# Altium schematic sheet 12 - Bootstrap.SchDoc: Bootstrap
size A3; PageSetup: Record=PageOptions¦CenterHorizontal=True¦CenterVertical=True¦PrintScale=1.01¦XCorrection=1.00¦YCorrection=1.00¦PrintKind=0¦BorderSize=5000000¦LeftOffset=0¦BottomOffset=0¦Orientation=2¦PaperLength=4200¦PaperWidth=2970¦Scale=100¦PaperSource=15¦PrintQuality=600¦MediaType=1¦DitherType=10¦PrintScaleMode=1¦PaperKind=A3¦PaperIndex=8; Author: Sébastien MEYER; SheetNumber: 12; SheetTotal: 14
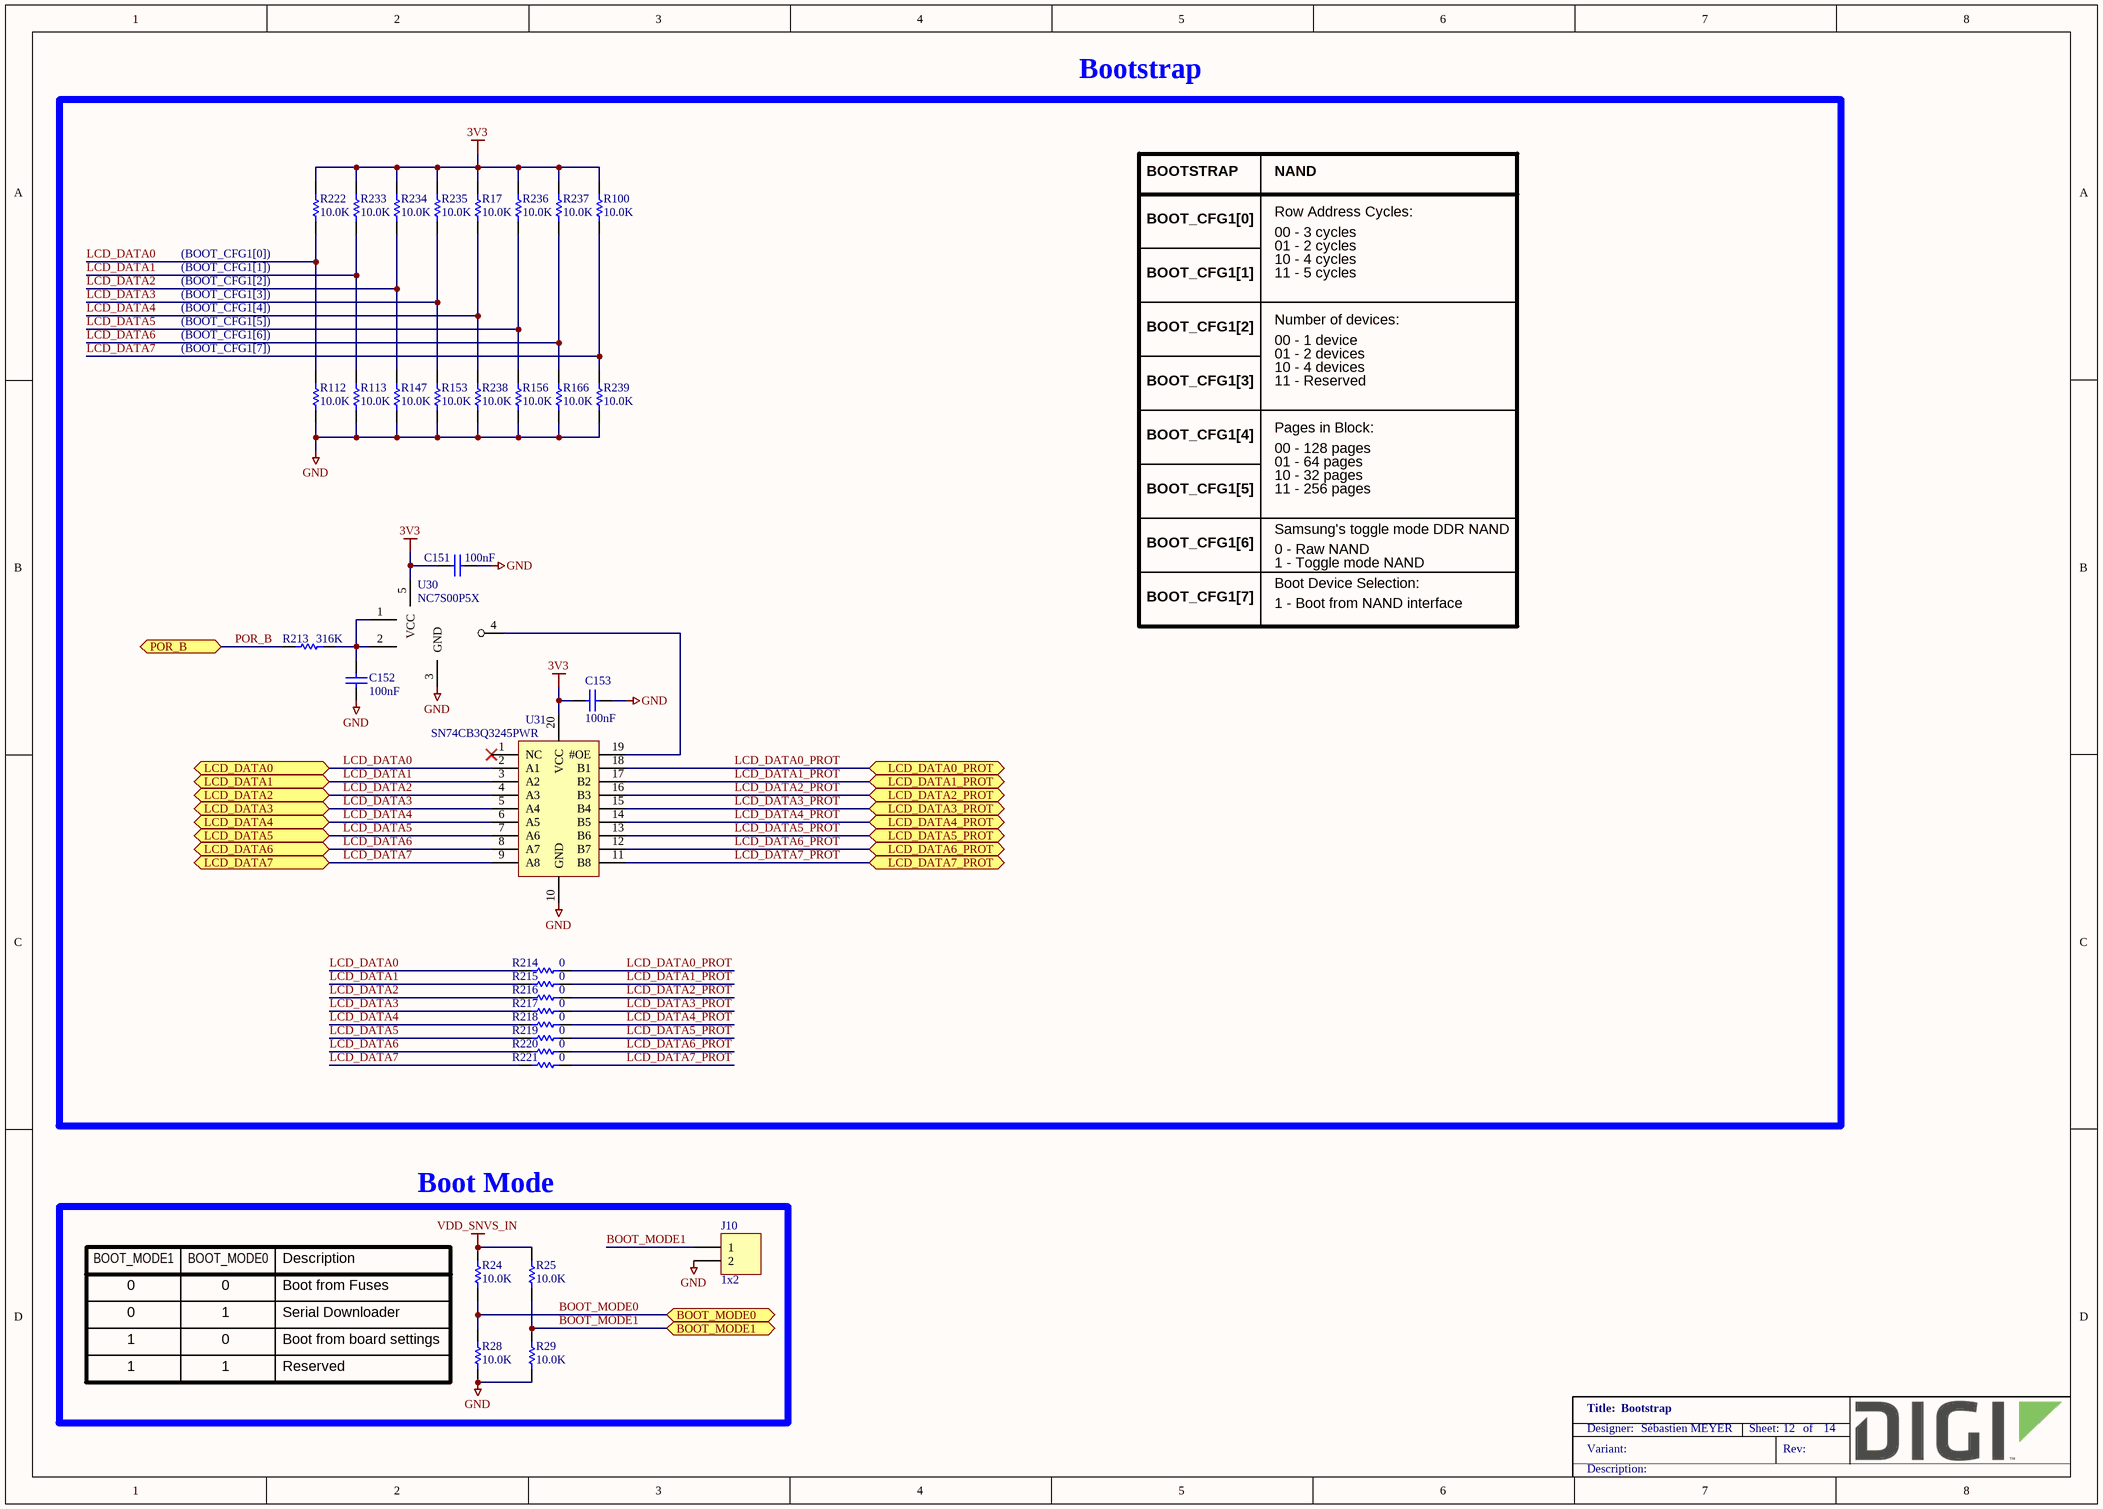
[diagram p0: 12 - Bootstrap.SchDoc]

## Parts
C151  100nF  [CAPC1005X55N]
C152  100nF  [CAPC1005X55N]
C153  100nF  [CAPC1005X55N]
J10  1x2  [FCI_68002-102HLF]
R17  10.0K  [RESC1005X40N]
R24  10.0K  [RESC1005X40N]
R25  10.0K  [RESC1005X40N]
R28  10.0K  [RESC1005X40N]
R29  10.0K  [RESC1005X40N]
R100  10.0K  [RESC1005X40N]
R112  10.0K  [RESC1005X40N]
R113  10.0K  [RESC1005X40N]
R147  10.0K  [RESC1005X40N]
R153  10.0K  [RESC1005X40N]
R156  10.0K  [RESC1005X40N]
R166  10.0K  [RESC1005X40N]
R213  316K  [RESC1609X55N]
R214  0  [RESC1005X40N]
R215  0  [RESC1005X40N]
R216  0  [RESC1005X40N]
R217  0  [RESC1005X40N]
R218  0  [RESC1005X40N]
R219  0  [RESC1005X40N]
R220  0  [RESC1005X40N]
R221  0  [RESC1005X40N]
R222  10.0K  [RESC1005X40N]
R233  10.0K  [RESC1005X40N]
R234  10.0K  [RESC1005X40N]
R235  10.0K  [RESC1005X40N]
R236  10.0K  [RESC1005X40N]
R237  10.0K  [RESC1005X40N]
R238  10.0K  [RESC1005X40N]
R239  10.0K  [RESC1005X40N]
U30  NC7S00P5X  [SOT65P210X110-5N]
U31  SN74CB3Q3245PWR  [SOP65P640X120-20N]

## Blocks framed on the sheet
Bootstrap: C151-C153 R17 R100 R112 R113 R147 R153 R156 R166 R213-R222 R233-R239 U30 U31
Boot Mode: J10 R24 R25 R28 R29

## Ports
BOOT_MODE0 (bidir), BOOT_MODE1 (bidir), LCD_DATA0 (bidir), LCD_DATA0_PROT (bidir), LCD_DATA1 (bidir), LCD_DATA1_PROT (bidir), LCD_DATA2 (bidir), LCD_DATA2_PROT (bidir), LCD_DATA3 (bidir), LCD_DATA3_PROT (bidir), LCD_DATA4 (bidir), LCD_DATA4_PROT (bidir), LCD_DATA5 (bidir), LCD_DATA5_PROT (bidir), LCD_DATA6 (bidir), LCD_DATA6_PROT (bidir), LCD_DATA7 (bidir), LCD_DATA7_PROT (bidir), POR_B (bidir)

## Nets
3V3: C151.1 C153.2 R17.2 R100.2 R222.2 R233.2 R234.2 R235.2 R236.2 R237.2 U30.5(VCC) U31.20(VCC)
GND: C151.2 C152.1 C153.1 J10.2 R28.2 R29.2 R112.1 R113.1 R147.1 R153.1 R156.1 R166.1 R238.1 R239.1 U30.3(GND) U31.10(GND)
VDD_SNVS_IN: R24.1 R25.1
BOOT_MODE0: R24.2 R28.1 ; port BOOT_MODE0
BOOT_MODE1: J10.1 R25.2 R29.1 ; port BOOT_MODE1
LCD_DATA0: R112.2 R214.1 R222.1 U31.2(A1) ; port LCD_DATA0
LCD_DATA0_PROT: R214.2 U31.18(B1) ; port LCD_DATA0_PROT
LCD_DATA1: R113.2 R215.1 R233.1 U31.3(A2) ; port LCD_DATA1
LCD_DATA1_PROT: R215.2 U31.17(B2) ; port LCD_DATA1_PROT
LCD_DATA2: R147.2 R216.1 R234.1 U31.4(A3) ; port LCD_DATA2
LCD_DATA2_PROT: R216.2 U31.16(B3) ; port LCD_DATA2_PROT
LCD_DATA3: R153.2 R217.1 R235.1 U31.5(A4) ; port LCD_DATA3
LCD_DATA3_PROT: R217.2 U31.15(B4) ; port LCD_DATA3_PROT
LCD_DATA4: R17.1 R218.1 R238.2 U31.6(A5) ; port LCD_DATA4
LCD_DATA4_PROT: R218.2 U31.14(B5) ; port LCD_DATA4_PROT
LCD_DATA5: R156.2 R219.1 R236.1 U31.7(A6) ; port LCD_DATA5
LCD_DATA5_PROT: R219.2 U31.13(B6) ; port LCD_DATA5_PROT
LCD_DATA6: R166.2 R220.1 R237.1 U31.8(A7) ; port LCD_DATA6
LCD_DATA6_PROT: R220.2 U31.12(B7) ; port LCD_DATA6_PROT
LCD_DATA7: R100.1 R221.1 R239.2 U31.9(A8) ; port LCD_DATA7
LCD_DATA7_PROT: R221.2 U31.11(B8) ; port LCD_DATA7_PROT
POR_B: R213.1 ; port POR_B
NetC152_2: C152.2 R213.2 U30.1(A) U30.2(B)
NetU30_4: U30.4(Y) U31.19(#OE)

Not connected (* = marked no-connect by the designer): U31 1(NC)*

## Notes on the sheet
- BOOTSTRAP
- NAND
- BOOT_CFG1[0]
- Row Address Cycles:
- 00 - 3 cycles
- (BOOT_CFG1[0])
- (BOOT_CFG1[1])
- (BOOT_CFG1[3])
- (BOOT_CFG1[4])
- (BOOT_CFG1[2])
- BOOT_CFG1[1]
- 01 - 2 cycles
- 10 - 4 cycles
- 11 - 5 cycles
- (BOOT_CFG1[6])
- (BOOT_CFG1[5])
- (BOOT_CFG1[7])
- BOOT_CFG1[2]
- Number of devices:
- 00 - 1 device
- 01 - 2 devices
- 10 - 4 devices
- BOOT_CFG1[3]
- BOOT_CFG1[4]
- 11 - Reserved
- Pages in Block:
- 00 - 128 pages
- BOOT_CFG1[5]
- 01 - 64 pages
- 10 - 32 pages
- 11 - 256 pages
- BOOT_CFG1[6]
- Samsung's toggle mode DDR NAND
- 0 - Raw NAND
- 1 - Toggle mode NAND
- Boot Device Selection:
- BOOT_CFG1[7]
- 1 - Boot from NAND interface
- BOOT_MODE1
- BOOT_MODE0
- Description
- 0
- 1
- Boot from Fuses
- Serial Downloader
- (near R28) Boot from board settings
- Reserved

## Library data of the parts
C151-C153 = 1000006: CAP 100nF 16V 10% X7R 0402; Part_Type: Capacitor; Manufacturer: Murata; Manufacturer_Part_Number: GRM155R71C104KA88D; Component_Life_Cycle_State: CAD Reviewed; Area: 0.95; Project: KITT; Tolerance: 10; Digi_PN: 14050552
J10 = 1001128: CONN HEADER 2POS .100" SGL GOLD; Part_Type: Connector; Manufacturer: Samtec; Manufacturer_Part_Number: TSW-102-07-G-S; Digi_PN: 00120002; Component_Life_Cycle_State: Reviewed; Area: 12.9032; Project: CCWMX6_SBC board
R17 R24 R25 R28 R29 R100 R112 R113 R147 R153 R156 R166 R222 R233-R239 = 1000537: RES 10.0K OHM 1/10W 1% 0402 SMD; Part_Type: Resistor; Manufacturer: Panasonic - ECG; Manufacturer_Part_Number: ERJ-2RKF1002X; Component_Life_Cycle_State: CAD Reviewed; Area: 0.95; Project: KITT; Power_WV_SRF: 100; Digi_PN: 13051084
R213 = 1001150: RES 316K OHM 1/10W 1% 0603 SMD; Part_Type: Resistor; Manufacturer: Yageo; Manufacturer_Part_Number: RC0603FR-07316KL; Digi_PN: 13050512; Component_Life_Cycle_State: Reviewed; Area: 1.5; Project: CCWMX6_SBC board; Power_WV_SRF: 100
R214-R221 = 1000076: RES 0.0 OHM 1/10W 0402 SMD; Part_Type: Resistor; Manufacturer: Panasonic - ECG; Manufacturer_Part_Number: ERJ-2GE0R00X; Component_Life_Cycle_State: Proven; Area: 0.95; Project: Adjustable Foundation; Power_WV_SRF: 10; Digi_PN: 13050387
U30 = 1001160: IC GATE NAND 2-INP HS LOG SC70-5; Manufacturer: Fairchild Semiconductor; Digi_PN: 16050675; Component_Life_Cycle_State: Reviewed; Area: 6.93; Project: CCWMX6_SBC board
U31 = 1001368: IC SWITCH BUS 8BIT FET 20-TSSOP; Manufacturer: Texas Instruments; Digi_PN: 16052042; Component_Life_Cycle_State: Reviewed; Area: 48,18; Project: ConnectCore i.MX6x SOM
